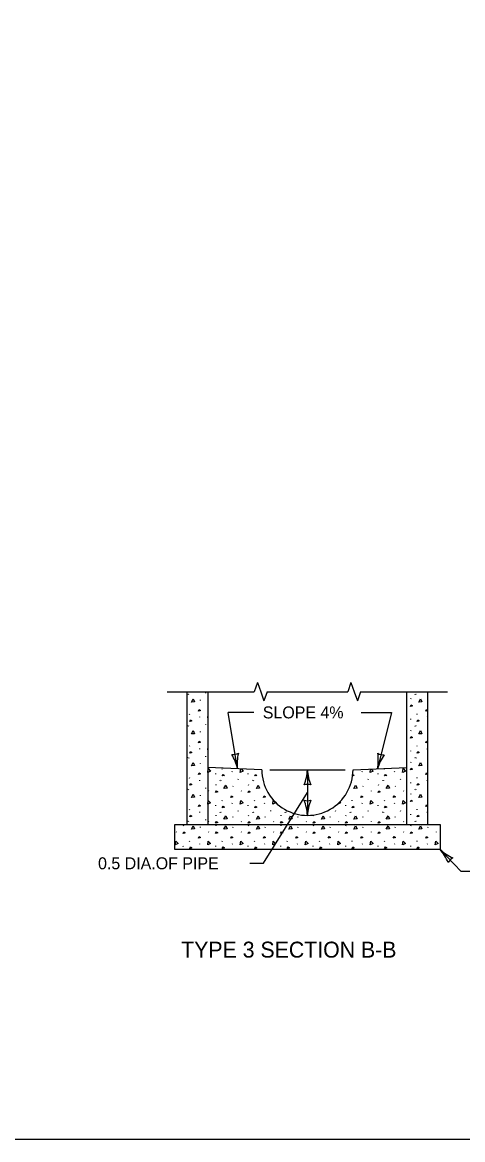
# Model space of a CAD drawing. Extents: x 49991.4 to 50028.3, y 49987.6 to 50011.4.
# Drawn here: x 50002.99 to 50005.21, y 49987.8 to 49993.41 of the extents above; entities that cross this region are included whole.
import ezdxf

# ---------------------------------------------------------------- set-up
doc = ezdxf.new("R2010")
doc.units = 0
for name, color, linetype in [('Level 1', 7, 'Continuous'), ('Level 2', 7, 'Continuous'), ('Level 3', 7, 'Continuous'), ('Level 6', 7, 'Continuous')]:
    doc.layers.add(name, color=color, linetype=linetype)

msp = doc.modelspace()

# ---------------------------------------------------------------- linework, layer by layer
at = {"layer": 'Level 1'}
for p, q in [((50003.8231, 49989.3815), (50003.8231, 49990.0482)), ((50003.8244, 49990.0366), (50003.8257, 49990.0346)), ((50003.8295, 49990.0358), (50003.8308, 49990.0338)), ((50003.9161, 49990.0405), (50003.9174, 49990.0435)), ((50003.9272, 49990.0482), (50003.9272, 49989.3815)), ((50004.9272, 49989.3815), (50004.9272, 49990.0482)), ((50004.9673, 49990.0366), (50004.9686, 49990.0346)), ((50004.9723, 49990.0358), (50004.9737, 49990.0338)), ((50005.0313, 49990.0482), (50005.0313, 49989.3815)), ((50003.8891, 49990.0042), (50003.8904, 49990.0072)), ((50004.9476, 49990.0119), (50004.9489, 49990.0149)), ((50003.8351, 49989.9333), (50003.8365, 49989.9363)), ((50003.8857, 49989.9197), (50003.8871, 49989.9227)), ((50004.978, 49989.9333), (50004.9793, 49989.9363)), ((50005.0286, 49989.9197), (50005.0299, 49989.9227)), ((50003.8244, 49989.8771), (50003.8257, 49989.8751)), ((50003.8295, 49989.8763), (50003.8308, 49989.8743)), ((50003.9161, 49989.881), (50003.9174, 49989.884)), ((50004.9445, 49989.9113), (50004.9449, 49989.9083)), ((50004.9673, 49989.8771), (50004.9686, 49989.8751)), ((50004.9723, 49989.8763), (50004.9737, 49989.8743)), ((50003.8891, 49989.8448), (50003.8904, 49989.8478)), ((50004.9476, 49989.8524), (50004.9489, 49989.8554)), ((50003.8351, 49989.7739), (50003.8365, 49989.7769)), ((50003.8857, 49989.7602), (50003.8871, 49989.7632)), ((50004.9445, 49989.7518), (50004.9449, 49989.7488)), ((50004.978, 49989.7739), (50004.9793, 49989.7769)), ((50005.0286, 49989.7602), (50005.0299, 49989.7632)), ((50003.8244, 49989.7177), (50003.8257, 49989.7157)), ((50003.8295, 49989.7169), (50003.8308, 49989.7149)), ((50003.9161, 49989.7216), (50003.9174, 49989.7245)), ((50004.9476, 49989.693), (50004.9489, 49989.696)), ((50004.9673, 49989.7177), (50004.9686, 49989.7157)), ((50004.9723, 49989.7169), (50004.9737, 49989.7149)), ((50003.8891, 49989.6853), (50003.8904, 49989.6883)), ((50004.1981, 49989.6561), (50003.9272, 49989.6674)), ((50003.9649, 49989.6378), (50003.9653, 49989.6348)), ((50003.9984, 49989.6598), (50003.9997, 49989.6628)), ((50004.049, 49989.6461), (50004.0503, 49989.6491)), ((50004.1282, 49989.6378), (50004.1285, 49989.6348)), ((50004.6564, 49989.6561), (50004.9272, 49989.6674)), ((50004.7021, 49989.6461), (50004.7034, 49989.6491)), ((50004.7813, 49989.6378), (50004.7816, 49989.6348)), ((50004.8147, 49989.6598), (50004.8161, 49989.6627)), ((50004.8653, 49989.6461), (50004.8667, 49989.6491)), ((50003.8351, 49989.6144), (50003.8365, 49989.6174)), ((50003.8857, 49989.6007), (50003.8871, 49989.6037)), ((50003.968, 49989.5789), (50003.9693, 49989.5819)), ((50003.9877, 49989.6036), (50003.989, 49989.6016)), ((50003.9927, 49989.6029), (50003.9941, 49989.6009)), ((50004.0793, 49989.6075), (50004.0807, 49989.6105)), ((50004.1313, 49989.5789), (50004.1326, 49989.5819)), ((50004.1509, 49989.6036), (50004.1523, 49989.6016)), ((50004.156, 49989.6029), (50004.1573, 49989.6009)), ((50004.7324, 49989.6075), (50004.7337, 49989.6105)), ((50004.7843, 49989.5789), (50004.7857, 49989.5819)), ((50004.804, 49989.6036), (50004.8053, 49989.6016)), ((50004.8091, 49989.6029), (50004.8104, 49989.6009)), ((50004.8957, 49989.6075), (50004.897, 49989.6105)), ((50004.9445, 49989.5924), (50004.9449, 49989.5894)), ((50004.978, 49989.6144), (50004.9793, 49989.6174)), ((50005.0286, 49989.6007), (50005.0299, 49989.6037)), ((50003.8244, 49989.5582), (50003.8257, 49989.5562)), ((50003.8295, 49989.5575), (50003.8308, 49989.5555)), ((50003.8891, 49989.5259), (50003.8904, 49989.5289)), ((50003.9161, 49989.5621), (50003.9174, 49989.5651)), ((50003.9307, 49989.5499), (50003.9321, 49989.5479)), ((50004.0523, 49989.5713), (50004.0537, 49989.5743)), ((50004.094, 49989.5499), (50004.0953, 49989.5479)), ((50004.7054, 49989.5713), (50004.7067, 49989.5743)), ((50004.7471, 49989.5499), (50004.7484, 49989.5479)), ((50004.8687, 49989.5713), (50004.87, 49989.5743)), ((50004.9103, 49989.5499), (50004.9117, 49989.5479)), ((50004.9476, 49989.5335), (50004.9489, 49989.5365)), ((50004.9673, 49989.5582), (50004.9686, 49989.5562)), ((50004.9723, 49989.5575), (50004.9737, 49989.5555)), ((50003.9649, 49989.4783), (50003.9653, 49989.4753)), ((50003.9984, 49989.5003), (50003.9997, 49989.5033)), ((50004.049, 49989.4867), (50004.0503, 49989.4897)), ((50004.1282, 49989.4783), (50004.1285, 49989.4753)), ((50004.1617, 49989.5003), (50004.163, 49989.5033)), ((50004.2123, 49989.4867), (50004.2136, 49989.4897)), ((50004.618, 49989.4783), (50004.6183, 49989.4753)), ((50004.6515, 49989.5003), (50004.6528, 49989.5033)), ((50004.7021, 49989.4867), (50004.7034, 49989.4897)), ((50004.7813, 49989.4783), (50004.7816, 49989.4753)), ((50004.8147, 49989.5003), (50004.8161, 49989.5033)), ((50004.8653, 49989.4867), (50004.8667, 49989.4897)), ((50003.8351, 49989.4549), (50003.8365, 49989.4579)), ((50003.8857, 49989.4413), (50003.8871, 49989.4443)), ((50003.968, 49989.4253), (50003.9693, 49989.4283)), ((50003.9877, 49989.4441), (50003.989, 49989.4421)), ((50003.9927, 49989.4434), (50003.9941, 49989.4414)), ((50004.0523, 49989.4176), (50004.0537, 49989.4206)), ((50004.0793, 49989.4481), (50004.0807, 49989.4511)), ((50004.1313, 49989.4253), (50004.1326, 49989.4283)), ((50004.1509, 49989.4441), (50004.1523, 49989.4421)), ((50004.156, 49989.4434), (50004.1573, 49989.4414)), ((50004.2156, 49989.4176), (50004.2169, 49989.4206)), ((50004.2426, 49989.4481), (50004.2439, 49989.4511)), ((50004.2945, 49989.4253), (50004.2959, 49989.4283)), ((50004.3142, 49989.4441), (50004.3155, 49989.4421)), ((50004.3193, 49989.4434), (50004.3206, 49989.4414)), ((50004.3789, 49989.4176), (50004.3802, 49989.4206)), ((50004.4578, 49989.4253), (50004.4591, 49989.4283)), ((50004.5421, 49989.4176), (50004.5435, 49989.4206)), ((50004.5691, 49989.4481), (50004.5705, 49989.4511)), ((50004.6211, 49989.4253), (50004.6224, 49989.4283)), ((50004.6407, 49989.4441), (50004.6421, 49989.4421)), ((50004.6458, 49989.4434), (50004.6471, 49989.4414)), ((50004.7054, 49989.4176), (50004.7067, 49989.4206)), ((50004.7324, 49989.4481), (50004.7337, 49989.4511)), ((50004.804, 49989.4441), (50004.8053, 49989.4421)), ((50004.8091, 49989.4434), (50004.8104, 49989.4414)), ((50004.8687, 49989.4176), (50004.87, 49989.4206)), ((50004.8957, 49989.4481), (50004.897, 49989.4511)), ((50004.9445, 49989.4329), (50004.9449, 49989.4299)), ((50004.978, 49989.4549), (50004.9793, 49989.4579)), ((50005.0286, 49989.4413), (50005.0299, 49989.4443)), ((50003.7605, 49989.3815), (50005.0938, 49989.3815)), ((50003.7605, 49989.3815), (50005.0938, 49989.3815)), ((50003.7605, 49989.3815), (50005.0938, 49989.3815)), ((50003.7605, 49989.2565), (50003.7605, 49989.3815)), ((50003.8047, 49989.3741), (50003.8061, 49989.3771)), ((50003.8244, 49989.3987), (50003.8257, 49989.3967)), ((50003.8295, 49989.398), (50003.8308, 49989.396)), ((50003.8891, 49989.3664), (50003.8904, 49989.3694)), ((50003.9161, 49989.4027), (50003.9174, 49989.4057)), ((50003.9307, 49989.3963), (50003.9321, 49989.3943)), ((50003.968, 49989.3741), (50003.9693, 49989.3771)), ((50004.0523, 49989.3664), (50004.0537, 49989.3694)), ((50004.094, 49989.3963), (50004.0953, 49989.3943)), ((50004.1313, 49989.3741), (50004.1326, 49989.3771)), ((50004.2156, 49989.3664), (50004.2169, 49989.3694)), ((50004.2573, 49989.3963), (50004.2586, 49989.3943)), ((50004.2945, 49989.3741), (50004.2959, 49989.3771)), ((50004.3789, 49989.3664), (50004.3802, 49989.3694)), ((50004.4205, 49989.3963), (50004.4219, 49989.3943)), ((50004.4578, 49989.3741), (50004.4591, 49989.3771)), ((50004.5421, 49989.3664), (50004.5435, 49989.3694)), ((50004.5838, 49989.3963), (50004.5851, 49989.3943)), ((50004.6211, 49989.3741), (50004.6224, 49989.3771)), ((50004.7054, 49989.3664), (50004.7067, 49989.3694)), ((50004.7471, 49989.3963), (50004.7484, 49989.3943)), ((50004.8687, 49989.3664), (50004.87, 49989.3694)), ((50004.9103, 49989.3963), (50004.9117, 49989.3943)), ((50004.9476, 49989.3741), (50004.9489, 49989.3771)), ((50004.9673, 49989.3987), (50004.9686, 49989.3967)), ((50004.9723, 49989.398), (50004.9737, 49989.396)), ((50005.0319, 49989.3664), (50005.0333, 49989.3694)), ((50005.0938, 49989.3815), (50005.0938, 49989.2565)), ((50003.7675, 49989.3451), (50003.7688, 49989.3431)), ((50003.9307, 49989.3451), (50003.9321, 49989.3431)), ((50004.094, 49989.3451), (50004.0953, 49989.3431)), ((50004.2573, 49989.3451), (50004.2586, 49989.3431)), ((50004.4205, 49989.3451), (50004.4219, 49989.3431)), ((50004.5838, 49989.3451), (50004.5851, 49989.3431)), ((50004.7471, 49989.3451), (50004.7484, 49989.3431)), ((50004.9103, 49989.3451), (50004.9117, 49989.3431)), ((50005.0736, 49989.3451), (50005.0749, 49989.3431)), ((50005.0938, 49989.2565), (50003.7605, 49989.2565)), ((50003.8017, 49989.2735), (50003.802, 49989.2705)), ((50003.8351, 49989.2955), (50003.8365, 49989.2985)), ((50003.8857, 49989.2818), (50003.8871, 49989.2848)), ((50003.9649, 49989.2735), (50003.9653, 49989.2705)), ((50003.9984, 49989.2955), (50003.9997, 49989.2985)), ((50004.049, 49989.2818), (50004.0503, 49989.2848)), ((50004.1282, 49989.2735), (50004.1285, 49989.2705)), ((50004.1617, 49989.2955), (50004.163, 49989.2985)), ((50004.2123, 49989.2818), (50004.2136, 49989.2848)), ((50004.2915, 49989.2735), (50004.2918, 49989.2705)), ((50004.3249, 49989.2955), (50004.3263, 49989.2985)), ((50004.3755, 49989.2818), (50004.3769, 49989.2848)), ((50004.4547, 49989.2735), (50004.4551, 49989.2705)), ((50004.4882, 49989.2955), (50004.4895, 49989.2985)), ((50004.5388, 49989.2818), (50004.5401, 49989.2848)), ((50004.618, 49989.2735), (50004.6183, 49989.2705)), ((50004.6515, 49989.2955), (50004.6528, 49989.2985)), ((50004.7021, 49989.2818), (50004.7034, 49989.2848)), ((50004.7813, 49989.2735), (50004.7816, 49989.2705)), ((50004.8147, 49989.2955), (50004.8161, 49989.2985)), ((50004.8653, 49989.2818), (50004.8667, 49989.2848)), ((50004.9445, 49989.2735), (50004.9449, 49989.2705)), ((50004.978, 49989.2955), (50004.9793, 49989.2985)), ((50005.0286, 49989.2818), (50005.0299, 49989.2848))]:
    msp.add_line(p, q, dxfattribs=at)
msp.add_lwpolyline([(49999.3835, 49998.9992), (50016.7501, 49998.9992), (50016.7501, 49987.7988), (49999.3835, 49987.7988)], close=True, dxfattribs=at)
for points in [[(50003.8441, 49989.9953), (50003.8531, 49990.0122), (50003.8601, 49989.9966), (50003.8445, 49989.9953)], [(50004.9453, 49989.9743), (50004.9493, 49989.9826), (50004.9559, 49989.9776), (50004.9453, 49989.9743)], [(50004.987, 49989.9953), (50004.996, 49990.0122), (50005.003, 49989.9966), (50004.9873, 49989.9953)], [(50003.8791, 49989.9505), (50003.8831, 49989.9588), (50003.8898, 49989.9538), (50003.8791, 49989.9505)], [(50003.9263, 49989.9162), (50003.9272, 49989.9229)], [(50005.022, 49989.9505), (50005.026, 49989.9588), (50005.0313, 49989.9548)], [(50005.0313, 49989.9533), (50005.022, 49989.9505)], [(50003.8358, 49989.8983), (50003.8398, 49989.9067), (50003.8465, 49989.9017), (50003.8358, 49989.8983)], [(50003.9272, 49989.9166), (50003.9266, 49989.9163)], [(50004.9787, 49989.8983), (50004.9827, 49989.9067), (50004.9893, 49989.9017), (50004.9787, 49989.8983)], [(50003.8441, 49989.8358), (50003.8531, 49989.8528), (50003.8601, 49989.8371), (50003.8445, 49989.8358)], [(50004.9453, 49989.8148), (50004.9493, 49989.8231), (50004.9559, 49989.8181), (50004.9453, 49989.8148)], [(50004.987, 49989.8358), (50004.996, 49989.8528), (50005.003, 49989.8371), (50004.9873, 49989.8358)], [(50003.8791, 49989.791), (50003.8831, 49989.7993), (50003.8898, 49989.7943), (50003.8791, 49989.791)], [(50003.9263, 49989.7567), (50003.9272, 49989.7635)], [(50003.9272, 49989.7571), (50003.9266, 49989.7569)], [(50005.022, 49989.791), (50005.026, 49989.7993), (50005.0313, 49989.7953)], [(50005.0313, 49989.7939), (50005.022, 49989.791)], [(50003.8358, 49989.7389), (50003.8398, 49989.7472), (50003.8465, 49989.7422), (50003.8358, 49989.7389)], [(50004.9787, 49989.7389), (50004.9827, 49989.7472), (50004.9893, 49989.7422), (50004.9787, 49989.7389)], [(50003.8441, 49989.6763), (50003.8531, 49989.6933), (50003.8601, 49989.6777), (50003.8445, 49989.6763)], [(50003.8791, 49989.6315), (50003.8831, 49989.6399), (50003.8898, 49989.6349), (50003.8791, 49989.6315)], [(50003.9263, 49989.6427), (50003.9289, 49989.6617), (50003.9408, 49989.6494), (50003.9266, 49989.6428)], [(50004.0895, 49989.6427), (50004.092, 49989.6605)], [(50004.0934, 49989.6605), (50004.1041, 49989.6494), (50004.0899, 49989.6428)], [(50004.7426, 49989.6427), (50004.7449, 49989.6598)], [(50004.747, 49989.6599), (50004.7571, 49989.6494), (50004.7429, 49989.6428)], [(50004.9059, 49989.6427), (50004.9085, 49989.6617), (50004.9204, 49989.6494), (50004.9062, 49989.6428)], [(50004.9453, 49989.6553), (50004.9493, 49989.6637), (50004.9559, 49989.6587), (50004.9453, 49989.6553)], [(50004.987, 49989.6763), (50004.996, 49989.6933), (50005.003, 49989.6777), (50004.9873, 49989.6763)], [(50005.022, 49989.6315), (50005.026, 49989.6399), (50005.0313, 49989.6359)], [(50003.8358, 49989.5794), (50003.8398, 49989.5877), (50003.8465, 49989.5827), (50003.8358, 49989.5794)], [(50003.9991, 49989.6248), (50004.0031, 49989.6331), (50004.0097, 49989.6281), (50003.9991, 49989.6248)], [(50004.1623, 49989.6248), (50004.1663, 49989.6331), (50004.173, 49989.6281), (50004.1623, 49989.6248)], [(50004.2032, 49989.6043), (50004.2033, 49989.6046)], [(50004.2034, 49989.6043), (50004.2032, 49989.6043)], [(50004.6562, 49989.6331), (50004.6628, 49989.6281), (50004.6562, 49989.6261)], [(50004.8154, 49989.6248), (50004.8194, 49989.6331), (50004.8261, 49989.6281), (50004.8154, 49989.6248)], [(50004.9787, 49989.5794), (50004.9827, 49989.5877), (50004.9893, 49989.5827), (50004.9787, 49989.5794)], [(50005.0313, 49989.6345), (50005.022, 49989.6315)], [(50003.8441, 49989.5169), (50003.8531, 49989.5339), (50003.8601, 49989.5182), (50003.8445, 49989.5169)], [(50003.9657, 49989.5413), (50003.9697, 49989.5496), (50003.9763, 49989.5446), (50003.9657, 49989.5413)], [(50004.0074, 49989.5623), (50004.0164, 49989.5793), (50004.0234, 49989.5636), (50004.0077, 49989.5623)], [(50004.0424, 49989.5175), (50004.0464, 49989.5258), (50004.0531, 49989.5208), (50004.0424, 49989.5175)], [(50004.1289, 49989.5413), (50004.1329, 49989.5496), (50004.1396, 49989.5446), (50004.1289, 49989.5413)], [(50004.1707, 49989.5623), (50004.1797, 49989.5793), (50004.1867, 49989.5636), (50004.171, 49989.5623)], [(50004.2057, 49989.5175), (50004.2097, 49989.5258), (50004.2163, 49989.5208), (50004.2057, 49989.5175)], [(50004.6605, 49989.5623), (50004.6695, 49989.5793), (50004.6765, 49989.5636), (50004.6608, 49989.5623)], [(50004.6955, 49989.5175), (50004.6995, 49989.5258), (50004.7061, 49989.5208), (50004.6955, 49989.5175)], [(50004.782, 49989.5413), (50004.786, 49989.5496), (50004.7927, 49989.5446), (50004.782, 49989.5413)], [(50004.8237, 49989.5623), (50004.8327, 49989.5793), (50004.8397, 49989.5636), (50004.8241, 49989.5623)], [(50004.8587, 49989.5175), (50004.8627, 49989.5258), (50004.8694, 49989.5208), (50004.8587, 49989.5175)], [(50004.987, 49989.5169), (50004.996, 49989.5339), (50005.003, 49989.5182), (50004.9873, 49989.5169)], [(50003.8791, 49989.4721), (50003.8831, 49989.4804), (50003.8898, 49989.4754), (50003.8791, 49989.4721)], [(50003.9263, 49989.4832), (50003.9289, 49989.5023), (50003.9408, 49989.4899), (50003.9266, 49989.4833)], [(50003.9991, 49989.4654), (50004.0031, 49989.4737), (50004.0097, 49989.4687), (50003.9991, 49989.4654)], [(50004.0895, 49989.4832), (50004.0922, 49989.5023), (50004.1041, 49989.4899), (50004.0899, 49989.4833)], [(50004.1623, 49989.4654), (50004.1663, 49989.4737), (50004.173, 49989.4687), (50004.1623, 49989.4654)], [(50004.2528, 49989.4832), (50004.2555, 49989.5023), (50004.2674, 49989.4899), (50004.2531, 49989.4833)], [(50004.5793, 49989.4832), (50004.5795, 49989.4841)], [(50004.5896, 49989.4944), (50004.5939, 49989.4899), (50004.5797, 49989.4833)], [(50004.6521, 49989.4654), (50004.6561, 49989.4737), (50004.6628, 49989.4687), (50004.6521, 49989.4654)], [(50004.7426, 49989.4832), (50004.7452, 49989.5023), (50004.7571, 49989.4899), (50004.7429, 49989.4833)], [(50004.8154, 49989.4654), (50004.8194, 49989.4737), (50004.8261, 49989.4687), (50004.8154, 49989.4654)], [(50004.9059, 49989.4832), (50004.9085, 49989.5023), (50004.9204, 49989.4899), (50004.9062, 49989.4833)], [(50004.9453, 49989.4959), (50004.9493, 49989.5042), (50004.9559, 49989.4992), (50004.9453, 49989.4959)], [(50005.022, 49989.4721), (50005.026, 49989.4804), (50005.0313, 49989.4765)], [(50005.0313, 49989.475), (50005.022, 49989.4721)], [(50003.8358, 49989.42), (50003.8398, 49989.4283), (50003.8465, 49989.4233), (50003.8358, 49989.42)], [(50004.0074, 49989.4086), (50004.0164, 49989.4256), (50004.0234, 49989.4099), (50004.0077, 49989.4086)], [(50004.1707, 49989.4086), (50004.1797, 49989.4256), (50004.1867, 49989.4099), (50004.171, 49989.4086)], [(50004.3339, 49989.4086), (50004.3429, 49989.4256), (50004.3499, 49989.4099), (50004.3343, 49989.4086)], [(50004.4972, 49989.4086), (50004.5062, 49989.4256), (50004.5132, 49989.4099), (50004.4975, 49989.4086)], [(50004.6605, 49989.4086), (50004.6695, 49989.4256), (50004.6765, 49989.4099), (50004.6608, 49989.4086)], [(50004.8237, 49989.4086), (50004.8327, 49989.4256), (50004.8397, 49989.4099), (50004.8241, 49989.4086)], [(50004.9787, 49989.42), (50004.9827, 49989.4283), (50004.9893, 49989.4233), (50004.9787, 49989.42)], [(50003.8441, 49989.3574), (50003.8531, 49989.3744), (50003.8601, 49989.3587), (50003.8445, 49989.3574)], [(50003.9657, 49989.3877), (50003.9697, 49989.396), (50003.9763, 49989.391), (50003.9657, 49989.3877)], [(50004.0074, 49989.3574), (50004.0164, 49989.3744), (50004.0234, 49989.3587), (50004.0077, 49989.3574)], [(50004.1289, 49989.3877), (50004.1329, 49989.396), (50004.1396, 49989.391), (50004.1289, 49989.3877)], [(50004.1707, 49989.3574), (50004.1797, 49989.3744), (50004.1867, 49989.3587), (50004.171, 49989.3574)], [(50004.2922, 49989.3877), (50004.2962, 49989.396), (50004.3029, 49989.391), (50004.2922, 49989.3877)], [(50004.3339, 49989.3574), (50004.3429, 49989.3744), (50004.3499, 49989.3587), (50004.3343, 49989.3574)], [(50004.4555, 49989.3877), (50004.4595, 49989.396), (50004.4661, 49989.391), (50004.4555, 49989.3877)], [(50004.4972, 49989.3574), (50004.5062, 49989.3744), (50004.5132, 49989.3587), (50004.4975, 49989.3574)], [(50004.6187, 49989.3877), (50004.6227, 49989.396), (50004.6294, 49989.391), (50004.6187, 49989.3877)], [(50004.6605, 49989.3574), (50004.6695, 49989.3744), (50004.6765, 49989.3587), (50004.6608, 49989.3574)], [(50004.782, 49989.3877), (50004.786, 49989.396), (50004.7927, 49989.391), (50004.782, 49989.3877)], [(50004.8237, 49989.3574), (50004.8327, 49989.3744), (50004.8397, 49989.3587), (50004.8241, 49989.3574)], [(50004.987, 49989.3574), (50004.996, 49989.3744), (50005.003, 49989.3587), (50004.9873, 49989.3574)], [(50003.8024, 49989.3365), (50003.8064, 49989.3448), (50003.8131, 49989.3398), (50003.8024, 49989.3365)], [(50003.8791, 49989.3126), (50003.8831, 49989.3209), (50003.8898, 49989.316), (50003.8791, 49989.3126)], [(50003.9657, 49989.3365), (50003.9697, 49989.3448), (50003.9763, 49989.3398), (50003.9657, 49989.3365)], [(50004.0424, 49989.3126), (50004.0464, 49989.3209), (50004.0531, 49989.316), (50004.0424, 49989.3126)], [(50004.1289, 49989.3365), (50004.1329, 49989.3448), (50004.1396, 49989.3398), (50004.1289, 49989.3365)], [(50004.2057, 49989.3126), (50004.2097, 49989.3209), (50004.2163, 49989.316), (50004.2057, 49989.3126)], [(50004.2922, 49989.3365), (50004.2962, 49989.3448), (50004.3029, 49989.3398), (50004.2922, 49989.3365)], [(50004.3689, 49989.3126), (50004.3729, 49989.3209), (50004.3796, 49989.316), (50004.3689, 49989.3126)], [(50004.4555, 49989.3365), (50004.4595, 49989.3448), (50004.4661, 49989.3398), (50004.4555, 49989.3365)], [(50004.5322, 49989.3126), (50004.5362, 49989.3209), (50004.5429, 49989.316), (50004.5322, 49989.3126)], [(50004.6187, 49989.3365), (50004.6227, 49989.3448), (50004.6294, 49989.3398), (50004.6187, 49989.3365)], [(50004.6955, 49989.3126), (50004.6995, 49989.3209), (50004.7061, 49989.316), (50004.6955, 49989.3126)], [(50004.782, 49989.3365), (50004.786, 49989.3448), (50004.7927, 49989.3398), (50004.782, 49989.3365)], [(50004.8587, 49989.3126), (50004.8627, 49989.3209), (50004.8694, 49989.316), (50004.8587, 49989.3126)], [(50004.9453, 49989.3365), (50004.9493, 49989.3448), (50004.9559, 49989.3398), (50004.9453, 49989.3365)], [(50005.022, 49989.3126), (50005.026, 49989.3209), (50005.0327, 49989.316), (50005.022, 49989.3126)], [(50003.763, 49989.2784), (50003.7657, 49989.2974), (50003.7776, 49989.2851), (50003.7633, 49989.2785)], [(50003.8358, 49989.2605), (50003.8398, 49989.2689), (50003.8465, 49989.2639), (50003.8358, 49989.2605)], [(50003.9263, 49989.2784), (50003.9289, 49989.2974), (50003.9408, 49989.2851), (50003.9266, 49989.2785)], [(50003.9991, 49989.2605), (50004.0031, 49989.2689), (50004.0097, 49989.2639), (50003.9991, 49989.2605)], [(50004.0895, 49989.2784), (50004.0922, 49989.2974), (50004.1041, 49989.2851), (50004.0899, 49989.2785)], [(50004.1623, 49989.2605), (50004.1663, 49989.2689), (50004.173, 49989.2639), (50004.1623, 49989.2605)], [(50004.2528, 49989.2784), (50004.2555, 49989.2974), (50004.2674, 49989.2851), (50004.2531, 49989.2785)], [(50004.3256, 49989.2605), (50004.3296, 49989.2689), (50004.3363, 49989.2639), (50004.3256, 49989.2605)], [(50004.4161, 49989.2784), (50004.4187, 49989.2974), (50004.4306, 49989.2851), (50004.4164, 49989.2785)], [(50004.4889, 49989.2605), (50004.4929, 49989.2689), (50004.4995, 49989.2639), (50004.4889, 49989.2605)], [(50004.5793, 49989.2784), (50004.582, 49989.2974), (50004.5939, 49989.2851), (50004.5797, 49989.2785)], [(50004.6521, 49989.2605), (50004.6561, 49989.2689), (50004.6628, 49989.2639), (50004.6521, 49989.2605)], [(50004.7426, 49989.2784), (50004.7452, 49989.2974), (50004.7571, 49989.2851), (50004.7429, 49989.2785)], [(50004.8154, 49989.2605), (50004.8194, 49989.2689), (50004.8261, 49989.2639), (50004.8154, 49989.2605)], [(50004.9059, 49989.2784), (50004.9085, 49989.2974), (50004.9204, 49989.2851), (50004.9062, 49989.2785)], [(50004.9787, 49989.2605), (50004.9827, 49989.2689), (50004.9893, 49989.2639), (50004.9787, 49989.2605)], [(50005.0691, 49989.2784), (50005.0718, 49989.2974), (50005.0837, 49989.2851), (50005.0695, 49989.2785)], [(50005.0847, 49989.2567), (50005.0846, 49989.2565)]]:
    msp.add_lwpolyline(points, dxfattribs=at)
msp.add_arc((50004.4272, 49989.6561), 0.2292, 180, 0.0005, dxfattribs=at)
at = {"layer": 'Level 3'}
for p, q in [((50004.1576, 49989.944), (50004.029, 49989.944)), ((50004.0758, 49989.6612), (50004.029, 49989.9431)), ((50004.697, 49989.944), (50004.8492, 49989.944)), ((50004.8492, 49989.9439), (50004.7791, 49989.6612)), ((50004.2381, 49989.6561), (50004.6164, 49989.6561)), ((50004.4272, 49989.6561), (50004.4272, 49989.4269)), ((50005.2001, 49989.1452), (50005.0938, 49989.2565)), ((50005.5197, 49989.1452), (50005.2001, 49989.1452))]:
    msp.add_line(p, q, dxfattribs=at)
msp.add_lwpolyline([(50004.1384, 49989.1865), (50004.2072, 49989.1865), (50004.4272, 49989.5415)], dxfattribs=at)
for centre, radius, start, end in [((50004.0549, 49989.7877), 0.0548, 261.5504, 297.2728), ((50003.8481, 49989.6118), 0.233, 12.2389, 31.4887), ((50004.2965, 49989.6885), 0.2223, 166.8676, 187.0511), ((50004.5504, 49989.706), 0.233, 348.9053, 8.1552), ((50004.9925, 49989.5989), 0.2223, 143.534, 163.7175), ((50004.8099, 49989.7857), 0.0548, 238.2168, 273.9392), ((50004.2051, 49989.6653), 0.2223, 337.456, 357.6395), ((50004.66, 49989.6676), 0.233, 182.8273, 202.0772), ((50004.4272, 49989.5279), 0.0548, 72.1388, 107.8612), ((50004.4272, 49989.5552), 0.0548, 252.1388, 287.8612), ((50004.1945, 49989.4154), 0.233, 2.8273, 22.0772), ((50004.6494, 49989.4178), 0.2223, 157.456, 177.6395), ((50004.9269, 49989.1097), 0.2223, 21.1397, 41.3232), ((50005.2542, 49989.4256), 0.233, 226.511, 245.7609), ((50005.1824, 49989.1638), 0.0548, 115.8225, 151.5449)]:
    msp.add_arc(centre, radius, start, end, dxfattribs=at)
at = {"layer": 'Level 6'}
for p, q in [((50004.1763, 49990.0939), (50004.1601, 49990.0482)), ((50004.1763, 49990.0939), (50004.1925, 49990.0482)), ((50004.6457, 49990.0939), (50004.6295, 49990.0482)), ((50004.6457, 49990.0939), (50004.6619, 49990.0482)), ((50003.7231, 49990.0482), (50004.1601, 49990.0482)), ((50004.1925, 49990.0482), (50004.2087, 49990.0025)), ((50004.2249, 49990.0482), (50004.2087, 49990.0025)), ((50004.2249, 49990.0482), (50004.6295, 49990.0482)), ((50004.6619, 49990.0482), (50004.6781, 49990.0025)), ((50004.6943, 49990.0482), (50004.6781, 49990.0025)), ((50004.6943, 49990.0482), (50005.1313, 49990.0482))]:
    msp.add_line(p, q, dxfattribs=at)

# ---------------------------------------------------------------- texts
at = {"layer": 'Level 2'}
for s, height, p in [('SLOPE 4%', 0.06, (50004.2029, 49989.914)), ('0.5 DIA.OF PIPE', 0.06, (50003.3749, 49989.1565)), ('TYPE 3 SECTION B-B', 0.08, (50003.7928, 49988.7129))]:
    msp.add_text(s, height=height, dxfattribs=at).set_placement(p)

doc.saveas('drawing.dxf')
